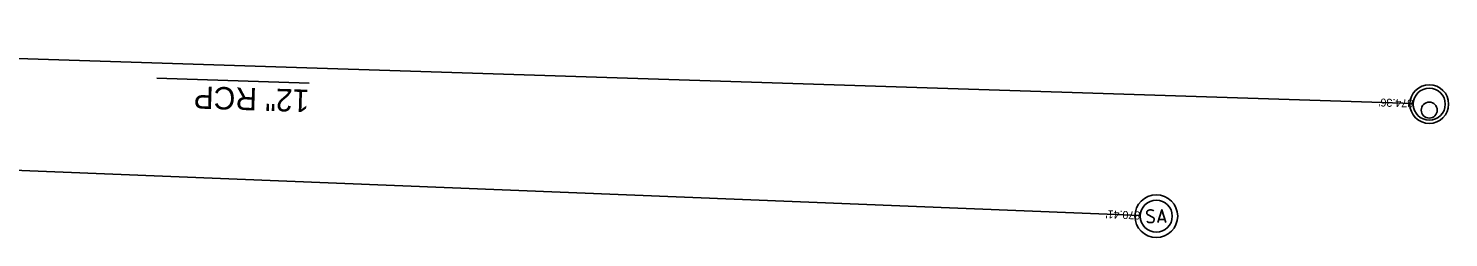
# Model space of a CAD drawing. Extents: x 1380440 to 1381945, y 468756 to 470369.
# Drawn here: x 1381767.2 to 1381944.7, y 470212 to 470238.1 of the extents above; entities that cross this region are included whole.
import ezdxf

# ---------------------------------------------------------------- set-up
doc = ezdxf.new("R2010")
doc.units = 0
for name, color, linetype in [('PV_P_Curb_Ramp', 7, 'Continuous'), ('PV_P_EOP', 7, 'Continuous'), ('PV_P_Joint', 7, 'Continuous'), ('RW_X_CL', 7, 'Continuous'), ('SC_Scratch1', 7, 'Continuous'), ('UT_X_Sanitary_Line', 7, 'Continuous'), ('X-CL', 7, 'Continuous')]:
    doc.layers.add(name, color=color, linetype=linetype)

msp = doc.modelspace()

# ---------------------------------------------------------------- linework, layer by layer
at = {"layer": 'PV_P_Curb_Ramp'}
for p, q in [((1381942.27, 470230.65), (1381942.27, 470230.65)), ((1381942.27, 470228.65), (1381942.27, 470228.65)), ((1381942.27, 470228.65), (1381942.27, 470228.65)), ((1381942.27, 470227.9), (1381942.27, 470227.9)), ((1381942.27, 470226.65), (1381942.27, 470226.65)), ((1381908.16, 470216.65), (1381908.16, 470216.65)), ((1381908.16, 470214.65), (1381908.16, 470214.65)), ((1381908.16, 470214.65), (1381908.16, 470214.65)), ((1381908.16, 470214.65), (1381908.16, 470214.65)), ((1381908.16, 470212.65), (1381908.16, 470212.65))]:
    msp.add_line(p, q, dxfattribs=at)
for centre in [(1381942.27, 470228.65), (1381908.16, 470214.65)]:
    msp.add_circle(centre, 2, dxfattribs=at)
at = {"layer": 'PV_P_EOP'}
for points in [[(1381907.83, 470215.33), (1381907.8, 470215.36), (1381907.76, 470215.38), (1381907.65, 470215.42), (1381907.51, 470215.45), (1381907.41, 470215.45), (1381907.37, 470215.45), (1381907.21, 470215.41), (1381907.07, 470215.33), (1381906.98, 470215.23), (1381906.96, 470215.13), (1381906.96, 470215.06), (1381906.98, 470214.96), (1381907.08, 470214.87), (1381907.78, 470214.49), (1381907.84, 470214.44), (1381907.86, 470214.39), (1381907.89, 470214.31), (1381907.89, 470214.24), (1381907.88, 470214.16), (1381907.86, 470214.11), (1381907.84, 470214.05), (1381907.81, 470214), (1381907.79, 470213.96), (1381907.75, 470213.92), (1381907.71, 470213.9), (1381907.66, 470213.87), (1381907.62, 470213.86), (1381907.51, 470213.85), (1381907.34, 470213.85), (1381907.22, 470213.87), (1381907.06, 470213.96), (1381906.96, 470214.04)], [(1381908.37, 470213.85), (1381908.87, 470215.45), (1381909.36, 470213.85)], [(1381909.24, 470214.22), (1381908.49, 470214.22)]]:
    msp.add_lwpolyline(points, dxfattribs=at)
for radius in [2.67, 2]:
    msp.add_circle((1381908.16, 470214.65), radius, dxfattribs=at)
at = {"layer": 'PV_P_Joint'}
for centre, radius in [((1381942.27, 470228.65), 2.42), ((1381942.27, 470228.65), 2), ((1381942.27, 470227.9), 1)]:
    msp.add_circle(centre, radius, dxfattribs=at)
at = {"layer": 'RW_X_CL'}
msp.add_line((1381783.25, 470231.88), (1381802.32, 470231.27), dxfattribs=at)
at = {"layer": 'UT_X_Sanitary_Line'}
msp.add_line((1381906.16, 470214.73), (1381603.06, 470226.96), dxfattribs=at)
at = {"layer": 'X-CL'}
msp.add_line((1381940.27, 470228.72), (1381649.42, 470238.11), dxfattribs=at)

# ---------------------------------------------------------------- texts
at = {"layer": 'RW_X_CL'}
msp.add_text('12" RCP', height=2.8, rotation=178.1508, dxfattribs=at).set_placement((1381802.36, 470230.44))
at = {"layer": 'SC_Scratch1'}
for s, rotation, p in [("874.36'", 178.1508, (1381940.28, 470229.22)), ("870.41'", 177.6889, (1381906.18, 470215.23))]:
    msp.add_text(s, height=1, rotation=rotation, dxfattribs=at).set_placement(p)

doc.saveas('drawing.dxf')
